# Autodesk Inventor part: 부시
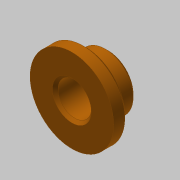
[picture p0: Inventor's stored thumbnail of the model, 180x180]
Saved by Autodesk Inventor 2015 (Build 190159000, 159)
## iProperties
Created: 2016-02
Part Number: 부시
Material: 스테인리스강
Document SubType Name: Modeling
Designer: mduedu
Density: 8.08 g/cm^3
Appearance: 주황색
Mass: 36.2061 g
Surface Area: 25.361 cm^2
Volume: 4.48096 cm^3
Author: mduedu
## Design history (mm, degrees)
sketch "스케치1"
  geometry: C1 r 15 at (0, 0); 1 further point
  constraints: 1 centre point, 1 coincident
  dimensions: "d0" = 30 diameter of C1
extrude "돌출1" new body sketch "스케치1" distance "d1" = 5; taper "d2" = 0 deg
sketch "스케치2"
  geometry: C1 r 10 at (0, 0); 1 further point
  constraints: 1 centre point, 1 coincident
  dimensions: "d3" = 20 diameter of C1
extrude "돌출2" join sketch "스케치2" distance "d4" = 8; taper "d5" = 0 deg
hole "구멍1" diameter "d8" = 12; stored, may be unused: countersink angle "d12" = 90 deg, drill point angle "d14" = 118 deg; dims "d9" = 6, "d10" = 4, "d11" = 2, "d13" = 8, "d15" = 10, "d16" = 10
chamfer "모따기1" distance "d17" = 1; stored, may be unused: second distance "d18" = 2, angle "d19" = 45 deg
chamfer "모따기2" distance "d20" = 1; stored, may be unused: second distance "d21" = 2, angle "d22" = 45 deg
chamfer "모따기3" distance "d23" = 1; stored, may be unused: second distance "d24" = 2, angle "d25" = 45 deg
node "솔리드1"
